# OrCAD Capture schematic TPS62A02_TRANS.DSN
size E; title: TPS62A02, 2-A High-Efficiency Synchronous; rev: 1.0; note: Datasheet: SLUSEG9B          EVM:SLUUCJ8; note: Synchronous Step Down Converter; note: Buck Converter in a SOT-563 Package
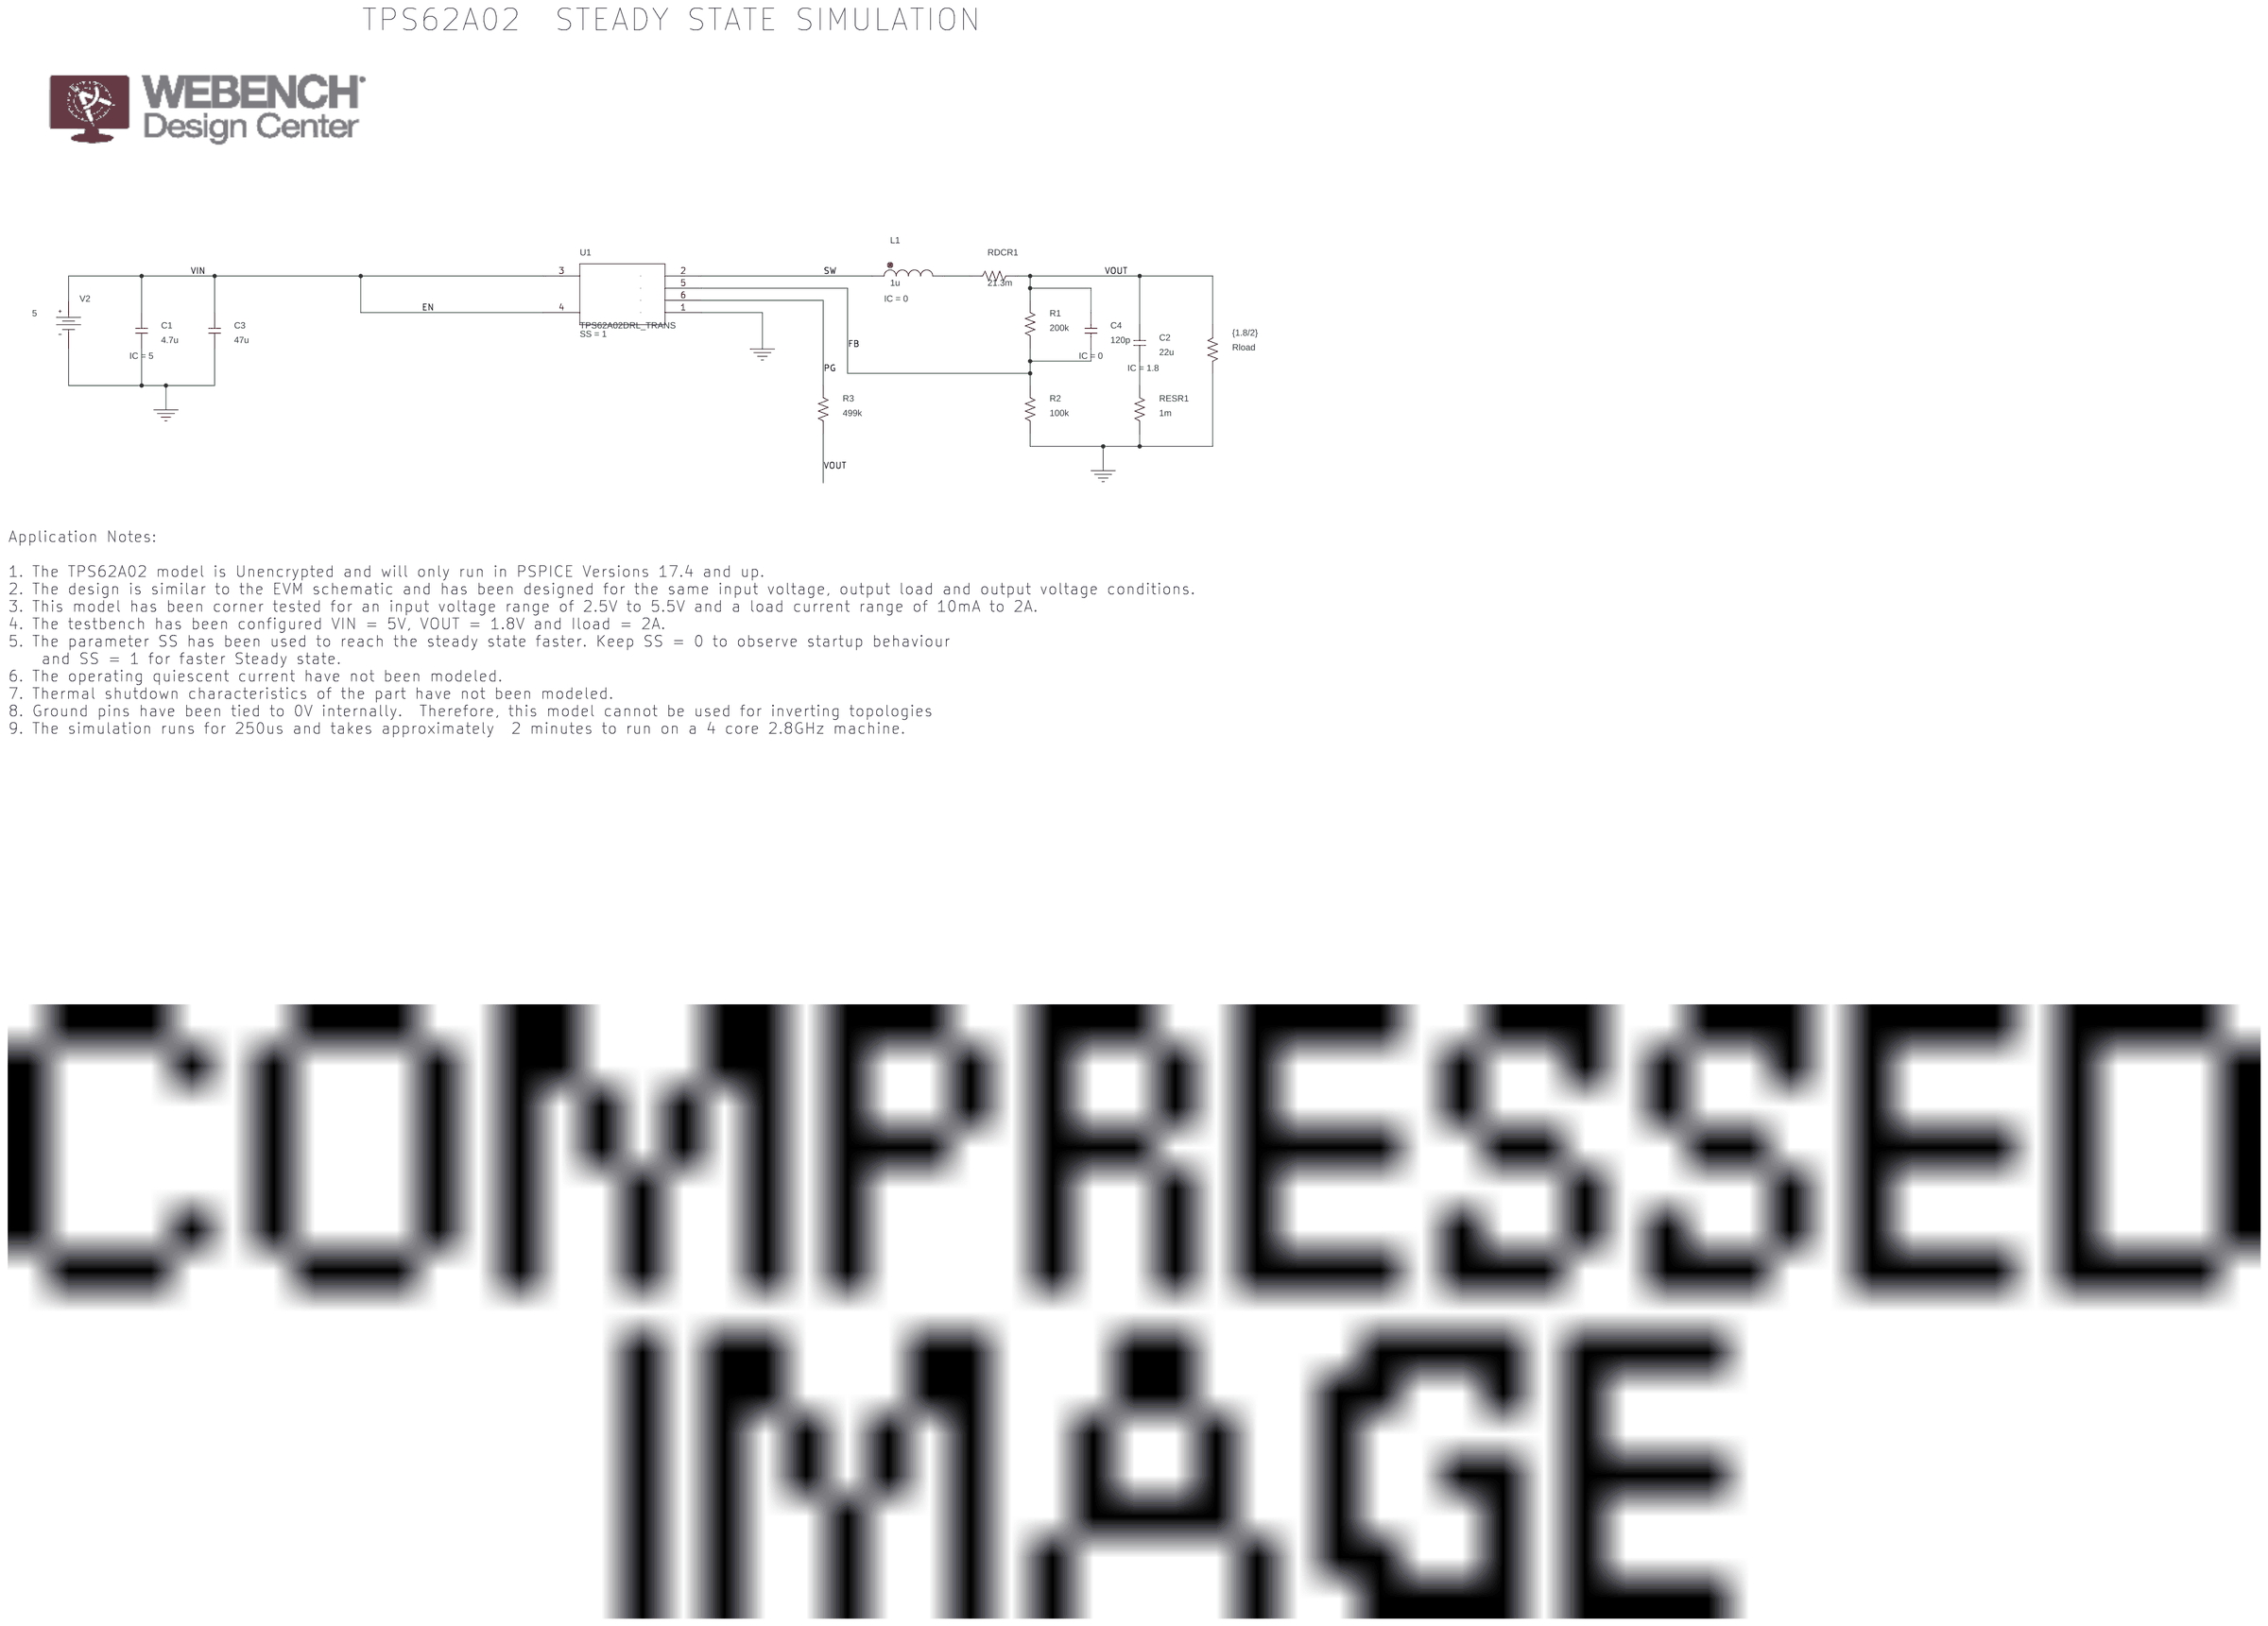
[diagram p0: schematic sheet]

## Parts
C1  4.7u  [RAD/CK05]
C2  22u  [RAD/CK05]
C3  47u  [RAD/CK05]
C4  120p  [RAD/CK05]
L1  1u  [DISC/.350x.175/LS.200x.100/.034]
R1  200k  [AX/RC05]
R2  100k  [AX/RC05]
R3  499k  [AX/RC05]
RDCR1  21.3m  [AX/RC05]
RESR1  1m  [AX/RC05]
Rload  {1.8/2}  [AX/RC05]
U1  TPS62A02DRL_TRANS  [DRL0006A-MFG]
V2  VDC

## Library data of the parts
C1 = C: IC: 5
C2 = C: IC: 1.8
C3 = C
C4 = C: IC: 0
L1 = L: IC: 0
R1-R3 RDCR1 RESR1 Rload = R
U1 = TPS62A02DRL_TRANS: SS: 1
V2 = VDC: DC: 5

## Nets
0: C1.1 C3.1 R2.1 RESR1.1 Rload.2 U1.1(GND) V2.1(-)
EN: C1.2 C3.2 U1.3(VIN) U1.4(EN) V2.0(+)
FB: C4.1 R1.1 R2.2 U1.5(FB)
PG: R3.2 U1.6(PG)
SW: L1.1 U1.2(SW)
VOUT: C2.2 C4.2 R1.2 R3.1 RDCR1.2 Rload.1
N16777988: L1.2 RDCR1.1
N16778116: C2.1 RESR1.2

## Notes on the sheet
- TPS62A02  STEADY STATE SIMULATION
- Application Notes:
  1. The TPS62A02 model is Unencrypted and will only run in PSPICE Versions 17.4 and up.
  2. The design is similar to the EVM schematic and has been designed for the same input voltage, output load and output voltage conditions.
  3. This model has been corner tested for an input voltage range of 2.5V to 5.5V and a load current range of 10mA to 2A.
  4. The testbench has been configured VIN = 5V, VOUT = 1.8V and Iload = 2A.
  5. The parameter SS has been used to reach the steady state faster. Keep SS = 0 to observe startup behaviour
      and SS = 1 for faster Steady state.
  6. The operating quiescent current have not been modeled.
  7. Thermal shutdown characteristics of the part have not been modeled.
  8. Ground pins have been tied to 0V internally.  Therefore, this model cannot be used for inverting topologies
  9. The simulation runs for 250us and takes approximately  2 minutes to run on a 4 core 2.8GHz machine.
